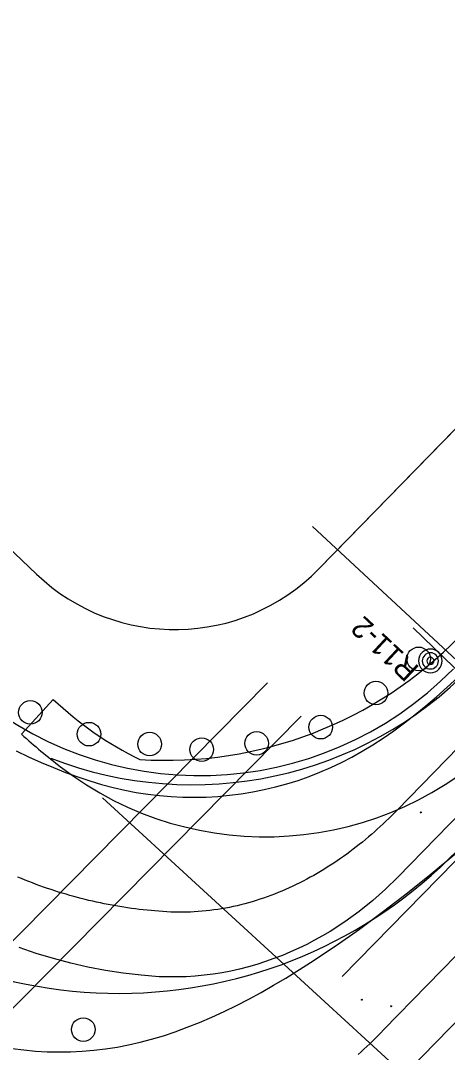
# Model space of a CAD drawing. Extents: x 2252379 to 2256472, y 13788212 to 13792539.
# Drawn here: x 2255447.1 to 2255483.2, y 13791367.7 to 13791455 of the extents above; entities that cross this region are included whole.
import ezdxf

# ---------------------------------------------------------------- set-up
doc = ezdxf.new("R2010")
doc.units = 0
for name, color, linetype in [('Bridge_Abutment', 7, 'Continuous'), ('D_DRN_AREA_X', 7, 'Continuous'), ('D_TCP_OVERALL_PATT', 7, 'Continuous'), ('D_TCP_PH_1_ATVEHICLE', 7, 'Continuous'), ('D_TCP_PH_1_BARREL', 7, 'Continuous'), ('D_TCP_PH_1_TEMP_PVMNT', 7, 'Continuous'), ('D_TCP_PH_1_WZPM_NRMV_4IN_W_SLD', 7, 'Continuous'), ('D_TCP_PH_1_WZPM_RMV_4IN_Y_SLD', 7, 'Continuous'), ('D_TCP_PH_1A_BARREL', 7, 'Continuous'), ('D_TCP_PH_1A_PATT', 7, 'Continuous'), ('D_TCP_PH_1B_BARREL', 7, 'Continuous'), ('D_TCP_PH_1B_PATT', 7, 'Continuous'), ('D_TCP_PH_2_SIGN', 7, 'Continuous'), ('D_TCP_PH_2_WZPM_NRMV_4IN_W_SLD', 7, 'Continuous'), ('E_Structure_Sign_Sign And Post Single_SGN', 7, 'Continuous'), ('Geom_Centerline', 7, 'Continuous'), ('SIGN_DESCR', 7, 'Continuous'), ('z - Construction', 7, 'Continuous')]:
    doc.layers.add(name, color=color, linetype=linetype)

# ---------------------------------------------------------------- blocks, each defined once
blk = doc.blocks.new('SGN')
at = {"layer": 'E_Structure_Sign_Sign And Post Single_SGN'}
blk.add_line((0.6, -0.2), (-0.6, -0.2), dxfattribs=at)
for radius in [0.2, 0.137, 0.0611]:
    blk.add_circle((0, 0), radius, dxfattribs=at)

msp = doc.modelspace()

# ---------------------------------------------------------------- linework, layer by layer
at = {"layer": 'Bridge_Abutment'}
for p, q in [((2255388.77, 13791318.7), (2255468, 13791398.96)), ((2255391.617, 13791315.89), (2255470.847, 13791396.15))]:
    msp.add_line(p, q, dxfattribs=at)
at = {"layer": 'D_DRN_AREA_X'}
msp.add_line((2255454.02, 13791389.236), (2255486.93, 13791359.056), dxfattribs=at)
at = {"layer": 'D_TCP_OVERALL_PATT'}
msp.add_line((2255692.066, 13791633.917), (2255472.331, 13791408.605), dxfattribs=at)
for points in [[(2255692.066, 13791633.917), (2255473.668, 13791409.976), (2255472.331, 13791408.605)], [(2255448.428, 13791408.173), (2255432.237, 13791423.614), (2255423.405, 13791430.567), (2255422.991, 13791430.892)]]:
    msp.add_lwpolyline(points, dxfattribs=at)
msp.add_circle((2255478.452, 13791371.582), 0.0417, dxfattribs=at)
msp.add_circle((2255478.452, 13791371.582), 0.0417, dxfattribs=at)
for centre, radius, start, end in [((2255460.16, 13791420.475), 17, 226.3568, 315.71793), ((2255460.16, 13791420.475), 17, 226.3568, 315.71793), ((2255462.257, 13791421.113), 30, 227.75639, 315.70035), ((2255462.257, 13791421.113), 30, 227.75639, 315.70035), ((2255462.257, 13791421.113), 30, 227.75639, 315.70035)]:
    msp.add_arc(centre, radius, start, end, dxfattribs=at)
at = {"layer": 'D_TCP_PH_1_ATVEHICLE'}
for p, q in [((2255477.825, 13791369.572), (2255544.76, 13791438.453)), ((2255520.826, 13791431.194), (2255478.972, 13791388.183))]:
    msp.add_line(p, q, dxfattribs=at)
for points in [[(2255446.716, 13791393.22), (2255447.768, 13791392.71), (2255448.818, 13791392.231), (2255449.862, 13791391.784), (2255450.898, 13791391.372), (2255451.925, 13791390.996), (2255452.941, 13791390.657), (2255453.942, 13791390.356), (2255454.929, 13791390.094), (2255455.903, 13791389.872), (2255456.881, 13791389.685), (2255457.861, 13791389.533), (2255458.844, 13791389.416), (2255459.831, 13791389.334), (2255460.82, 13791389.286), (2255461.811, 13791389.272), (2255462.801, 13791389.294), (2255463.791, 13791389.35), (2255464.777, 13791389.441), (2255465.76, 13791389.566), (2255466.738, 13791389.726), (2255467.71, 13791389.919), (2255468.675, 13791390.147), (2255469.631, 13791390.409), (2255470.578, 13791390.704), (2255471.513, 13791391.031), (2255472.436, 13791391.391), (2255473.347, 13791391.784), (2255474.247, 13791392.21), (2255475.134, 13791392.669), (2255476.016, 13791393.165), (2255476.903, 13791393.704), (2255477.796, 13791394.286), (2255478.692, 13791394.909), (2255479.593, 13791395.572), (2255480.496, 13791396.274), (2255481.402, 13791397.012), (2255482.309, 13791397.783), (2255483.217, 13791398.586), (2255485.035, 13791400.276)], [(2255487.72, 13791391.437), (2255479.036, 13791382.513), (2255477.996, 13791381.502), (2255476.898, 13791380.529), (2255475.744, 13791379.602), (2255474.539, 13791378.728), (2255473.284, 13791377.914), (2255472.639, 13791377.53), (2255471.982, 13791377.164), (2255471.314, 13791376.815), (2255470.635, 13791376.485), (2255469.947, 13791376.173), (2255469.248, 13791375.88), (2255468.541, 13791375.607), (2255467.825, 13791375.354), (2255467.102, 13791375.123), (2255466.371, 13791374.912), (2255465.633, 13791374.725), (2255464.89, 13791374.559), (2255464.142, 13791374.416), (2255463.389, 13791374.297), (2255462.632, 13791374.2), (2255461.873, 13791374.128), (2255461.111, 13791374.08), (2255460.348, 13791374.056), (2255459.585, 13791374.057), (2255458.821, 13791374.082), (2255457.298, 13791374.202), (2255455.782, 13791374.382), (2255454.277, 13791374.614), (2255452.791, 13791374.896), (2255451.327, 13791375.227), (2255449.866, 13791375.611), (2255448.409, 13791376.049), (2255446.964, 13791376.54)], [(2255478.972, 13791388.183), (2255478.738, 13791387.946), (2255478.501, 13791387.711), (2255478.263, 13791387.478), (2255478.022, 13791387.247), (2255477.78, 13791387.019), (2255477.535, 13791386.793), (2255477.288, 13791386.569), (2255477.039, 13791386.347), (2255476.788, 13791386.128), (2255476.535, 13791385.911), (2255476.279, 13791385.697), (2255476.022, 13791385.485), (2255475.762, 13791385.276), (2255475.5, 13791385.07), (2255475.236, 13791384.866), (2255474.97, 13791384.665), (2255474.702, 13791384.467), (2255474.432, 13791384.272), (2255474.159, 13791384.08), (2255473.885, 13791383.891), (2255473.608, 13791383.705), (2255473.329, 13791383.523), (2255473.048, 13791383.343), (2255472.766, 13791383.167), (2255472.48, 13791382.994), (2255472.193, 13791382.825), (2255471.904, 13791382.659), (2255471.613, 13791382.496), (2255471.32, 13791382.338), (2255471.025, 13791382.182), (2255470.728, 13791382.031), (2255470.429, 13791381.883), (2255470.128, 13791381.74), (2255469.826, 13791381.6), (2255469.521, 13791381.464), (2255469.215, 13791381.333), (2255468.907, 13791381.205), (2255468.598, 13791381.082), (2255468.286, 13791380.962), (2255467.973, 13791380.848), (2255467.659, 13791380.737), (2255467.343, 13791380.631), (2255467.025, 13791380.53), (2255466.706, 13791380.433), (2255466.386, 13791380.341), (2255466.064, 13791380.253), (2255465.742, 13791380.17), (2255465.417, 13791380.092), (2255465.092, 13791380.019), (2255464.766, 13791379.951), (2255464.439, 13791379.888), (2255464.11, 13791379.83), (2255463.781, 13791379.777), (2255463.451, 13791379.729), (2255463.121, 13791379.686), (2255462.79, 13791379.649), (2255462.458, 13791379.617), (2255462.126, 13791379.59), (2255461.793, 13791379.569), (2255461.46, 13791379.553), (2255461.127, 13791379.543), (2255460.793, 13791379.538), (2255460.46, 13791379.539), (2255460.127, 13791379.545), (2255459.794, 13791379.557), (2255459.461, 13791379.575), (2255459.128, 13791379.596), (2255458.796, 13791379.619), (2255458.463, 13791379.646), (2255458.131, 13791379.676), (2255457.8, 13791379.708), (2255457.468, 13791379.743), (2255457.137, 13791379.782), (2255456.806, 13791379.823), (2255456.476, 13791379.867), (2255456.146, 13791379.914), (2255455.816, 13791379.963), (2255455.487, 13791380.016), (2255455.159, 13791380.072), (2255454.83, 13791380.13), (2255454.503, 13791380.192), (2255454.176, 13791380.256), (2255453.849, 13791380.323), (2255453.523, 13791380.393), (2255453.198, 13791380.466), (2255452.873, 13791380.542), (2255452.549, 13791380.62), (2255452.226, 13791380.702), (2255451.904, 13791380.786), (2255451.582, 13791380.873), (2255451.261, 13791380.963), (2255450.941, 13791381.055), (2255450.621, 13791381.151), (2255450.303, 13791381.249), (2255449.985, 13791381.35), (2255449.669, 13791381.454), (2255449.353, 13791381.561), (2255449.038, 13791381.67), (2255448.724, 13791381.783), (2255448.411, 13791381.898), (2255448.099, 13791382.015), (2255447.788, 13791382.136), (2255447.479, 13791382.259), (2255447.17, 13791382.385), (2255446.862, 13791382.513)], [(2255446.378, 13791368.001), (2255447.361, 13791367.876), (2255448.347, 13791367.785), (2255449.337, 13791367.729), (2255450.327, 13791367.707), (2255451.318, 13791367.72), (2255452.307, 13791367.768), (2255453.294, 13791367.85), (2255454.278, 13791367.967), (2255455.257, 13791368.119), (2255456.234, 13791368.306), (2255457.207, 13791368.527), (2255458.184, 13791368.786), (2255459.178, 13791369.085), (2255460.184, 13791369.423), (2255461.203, 13791369.798), (2255462.231, 13791370.21), (2255463.268, 13791370.656), (2255464.31, 13791371.136), (2255465.355, 13791371.647), (2255466.402, 13791372.187), (2255467.45, 13791372.755), (2255468.498, 13791373.349), (2255469.545, 13791373.967), (2255471.632, 13791375.271), (2255473.707, 13791376.655), (2255475.768, 13791378.108), (2255477.814, 13791379.622), (2255479.844, 13791381.188), (2255481.858, 13791382.799), (2255483.857, 13791384.45)], [(2255475.661, 13791367.495), (2255475.909, 13791367.718), (2255476.156, 13791367.942), (2255476.401, 13791368.168), (2255476.643, 13791368.397), (2255476.884, 13791368.628), (2255477.122, 13791368.861), (2255477.359, 13791369.095), (2255477.593, 13791369.332), (2255477.825, 13791369.572)]]:
    msp.add_lwpolyline(points, dxfattribs=at)
for centre in [(2255480.963, 13791387.986), (2255480.963, 13791387.986), (2255475.978, 13791372.122), (2255475.978, 13791372.122)]:
    msp.add_circle(centre, 0.0417, dxfattribs=at)
at = {"layer": 'D_TCP_PH_1_BARREL'}
for centre in [(2255480.787, 13791400.992), (2255477.174, 13791398.1), (2255447.915, 13791396.461), (2255472.498, 13791395.213), (2255452.881, 13791394.616), (2255458.013, 13791393.778), (2255467.073, 13791393.839), (2255462.423, 13791393.311)]:
    msp.add_circle(centre, 1, dxfattribs=at)
at = {"layer": 'D_TCP_PH_1_TEMP_PVMNT'}
msp.add_line((2255449.854, 13791397.567), (2255447.169, 13791394.604), dxfattribs=at)
for centre, radius, start, end in [((2255459.416, 13791427.038), 34.637, 266.30548, 315.78176), ((2255470.141, 13791418.944), 29.471, 226.4991, 243.91935), ((2255488.278, 13791440.551), 61.652, 228.18134, 232.21805), ((2255467.824, 13791414.265), 28.337, 232.25583, 315.82092)]:
    msp.add_arc(centre, radius, start, end, dxfattribs=at)
at = {"layer": 'D_TCP_PH_1_WZPM_NRMV_4IN_W_SLD'}
msp.add_arc((2255461.628, 13791423.332), 33, 248.71476, 315.70035, dxfattribs=at)
at = {"layer": 'D_TCP_PH_1_WZPM_RMV_4IN_Y_SLD'}
msp.add_arc((2255455.412, 13791412.667), 40, 224.52752, 315.70035, dxfattribs=at)
at = {"layer": 'D_TCP_PH_1A_BARREL'}
msp.add_circle((2255452.396, 13791369.602), 1, dxfattribs=at)
msp.add_circle((2255452.396, 13791369.602), 1, dxfattribs=at)
at = {"layer": 'D_TCP_PH_1A_PATT'}
for p, q in [((2255692.066, 13791633.917), (2255473.668, 13791409.976)), ((2255473.668, 13791409.976), (2255472.331, 13791408.605))]:
    msp.add_line(p, q, dxfattribs=at)
msp.add_lwpolyline([(2255448.428, 13791408.173), (2255432.237, 13791423.614), (2255423.405, 13791430.567), (2255422.991, 13791430.892)], dxfattribs=at)
for centre, radius, start, end in [((2255460.16, 13791420.475), 17, 226.3568, 315.71793), ((2255462.257, 13791421.113), 30, 227.75639, 315.70035)]:
    msp.add_arc(centre, radius, start, end, dxfattribs=at)
at = {"layer": 'D_TCP_PH_1B_BARREL'}
msp.add_circle((2255452.396, 13791369.602), 1, dxfattribs=at)
at = {"layer": 'D_TCP_PH_1B_PATT'}
msp.add_arc((2255462.257, 13791421.113), 30, 227.75639, 315.70035, dxfattribs=at)
at = {"layer": 'D_TCP_PH_2_WZPM_NRMV_4IN_W_SLD'}
msp.add_lwpolyline([(2255420.402, 13791305.163), (2255629.915, 13791519.883)], dxfattribs=at)
at = {"layer": 'Geom_Centerline'}
msp.add_line((2255474.316, 13791374.097), (2255584.953, 13791487.208), dxfattribs=at)
at = {"layer": 'z - Construction'}
msp.add_line((2255471.812, 13791412.21), (2255490, 13791395.289), dxfattribs=at)

# ---------------------------------------------------------------- block references
at = {"layer": 'D_TCP_PH_2_SIGN', "xscale": 5.000000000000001, "yscale": -5.000000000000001, "rotation": -44.222909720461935}
msp.add_blockref('SGN', (2255481.784, 13791400.822), dxfattribs=at)

# ---------------------------------------------------------------- texts
at = {"layer": 'SIGN_DESCR'}
msp.add_text('R11-2', height=1.8, rotation=137.0101, dxfattribs=at).set_placement((2255480.928, 13791400.249))

doc.saveas('drawing.dxf')
